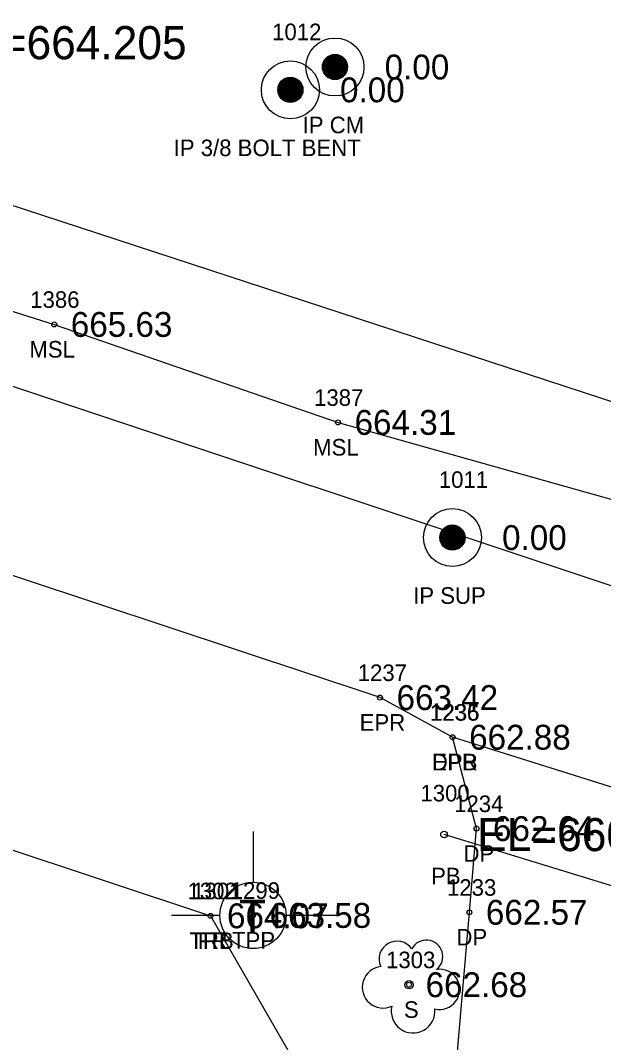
# Model space of a CAD drawing. Extents: x 1655137 to 1657928, y 1003994 to 1005407.
# Drawn here: x 1656195.9 to 1656231.1, y 1004645.1 to 1004706.8 of the extents above; entities that cross this region are included whole.
import ezdxf

# ---------------------------------------------------------------- set-up
doc = ezdxf.new("R2010")
doc.units = 0
for name, color, linetype in [('RD_EX_DR_Pipe', 7, 'Continuous'), ('RD_EX_DR_Pipe_txCode', 7, 'Continuous'), ('RD_EX_Driveway', 7, 'Continuous'), ('RD_EX_Driveway_txCode', 7, 'Continuous'), ('RD_EX_DV_Prop_txCode', 7, 'Continuous'), ('RD_EX_DV_PropPin', 7, 'Continuous'), ('RD_EX_Fence_Other', 7, 'Continuous'), ('RD_EX_Fence_Other_txCode', 7, 'Continuous'), ('RD_EX_Misc', 7, 'Continuous'), ('RD_EX_Misc_txCode', 7, 'Continuous'), ('RD_EX_Road', 7, 'Continuous'), ('RD_EX_Road_txCode', 7, 'Continuous'), ('RD_EX_TX_Driveway_ELEV', 7, 'Continuous'), ('RD_EX_TX_DV_Prop_ELEV', 7, 'Continuous'), ('RD_EX_TX_Fence_Other_ELEV', 7, 'Continuous'), ('RD_EX_TX_Misc_ELEV', 7, 'Continuous'), ('RD_EX_TX_Road_ELEV', 7, 'Continuous'), ('RD_EX_TX_UT_ELEV', 7, 'Continuous'), ('RD_EX_TX_VEG_ELEV', 7, 'Continuous'), ('RD_EX_UT', 7, 'Continuous'), ('RD_EX_UT_txCode', 7, 'Continuous'), ('RD_EX_VEG', 7, 'Continuous'), ('RD_EX_VEG_txCode', 7, 'Continuous'), ('RD_HC_Cl', 7, 'Continuous'), ('RD_SMD_Locator', 7, 'Continuous'), ('RD_TX_Pipe_ElevEX', 7, 'Continuous')]:
    doc.layers.add(name, color=color, linetype=linetype)

msp = doc.modelspace()

# ---------------------------------------------------------------- linework, layer by layer
at = {"layer": 'RD_EX_DR_Pipe'}
msp.add_line((1656241.451, 1004651.596), (1656221.513, 1004657.692), dxfattribs=at)
at = {"layer": 'RD_EX_Driveway'}
msp.add_lwpolyline([(1656244.505, 1004656.516), (1656239.142, 1004653.107), (1656236.385, 1004648.454), (1656232.371, 1004638.136), (1656222.105, 1004642.026), (1656223.042, 1004652.998), (1656223.472, 1004658.051), (1656222.03, 1004663.569)], dxfattribs=at)
at = {"layer": 'RD_EX_DV_PropPin'}
for p, q in [((1656214.263, 1004703.667), (1656214.263, 1004704.406)), ((1656214.298, 1004703.61), (1656214.298, 1004704.463)), ((1656214.333, 1004703.562), (1656214.333, 1004704.51)), ((1656214.368, 1004703.521), (1656214.368, 1004704.551)), ((1656214.403, 1004703.485), (1656214.403, 1004704.587)), ((1656214.438, 1004703.454), (1656214.438, 1004704.618)), ((1656214.473, 1004703.426), (1656214.473, 1004704.646)), ((1656214.508, 1004703.402), (1656214.508, 1004704.671)), ((1656214.543, 1004703.38), (1656214.543, 1004704.693)), ((1656214.578, 1004703.361), (1656214.578, 1004704.712)), ((1656214.613, 1004703.343), (1656214.613, 1004704.729)), ((1656214.648, 1004703.329), (1656214.648, 1004704.744)), ((1656214.683, 1004703.316), (1656214.683, 1004704.757)), ((1656214.718, 1004703.305), (1656214.718, 1004704.768)), ((1656214.753, 1004703.296), (1656214.753, 1004704.777)), ((1656214.788, 1004703.288), (1656214.788, 1004704.784)), ((1656214.823, 1004703.282), (1656214.823, 1004704.79)), ((1656214.858, 1004703.278), (1656214.858, 1004704.794)), ((1656214.893, 1004703.276), (1656214.893, 1004704.796)), ((1656214.928, 1004703.275), (1656214.928, 1004704.797)), ((1656214.963, 1004703.276), (1656214.963, 1004704.796)), ((1656214.998, 1004703.278), (1656214.998, 1004704.794)), ((1656215.033, 1004703.282), (1656215.033, 1004704.79)), ((1656215.068, 1004703.288), (1656215.068, 1004704.784)), ((1656215.103, 1004703.296), (1656215.103, 1004704.777)), ((1656215.138, 1004703.305), (1656215.138, 1004704.768)), ((1656215.173, 1004703.316), (1656215.173, 1004704.757)), ((1656215.208, 1004703.329), (1656215.208, 1004704.744)), ((1656215.243, 1004703.343), (1656215.243, 1004704.729)), ((1656215.278, 1004703.361), (1656215.278, 1004704.712)), ((1656215.313, 1004703.38), (1656215.313, 1004704.693)), ((1656215.348, 1004703.402), (1656215.348, 1004704.671)), ((1656215.383, 1004703.426), (1656215.383, 1004704.646)), ((1656215.418, 1004703.454), (1656215.418, 1004704.618)), ((1656215.453, 1004703.485), (1656215.453, 1004704.587)), ((1656215.488, 1004703.521), (1656215.488, 1004704.551)), ((1656215.523, 1004703.562), (1656215.523, 1004704.51)), ((1656215.558, 1004703.61), (1656215.558, 1004704.463)), ((1656215.593, 1004703.667), (1656215.593, 1004704.406)), ((1656214.193, 1004703.84), (1656214.193, 1004704.232)), ((1656214.228, 1004703.738), (1656214.228, 1004704.334)), ((1656215.628, 1004703.738), (1656215.628, 1004704.334)), ((1656215.663, 1004703.84), (1656215.663, 1004704.232)), ((1656211.674, 1004702.14), (1656211.674, 1004703.17)), ((1656211.709, 1004702.105), (1656211.709, 1004703.206)), ((1656211.744, 1004702.073), (1656211.744, 1004703.238)), ((1656211.779, 1004702.046), (1656211.779, 1004703.265)), ((1656211.814, 1004702.021), (1656211.814, 1004703.29)), ((1656211.849, 1004701.999), (1656211.849, 1004703.312)), ((1656211.884, 1004701.98), (1656211.884, 1004703.331)), ((1656211.919, 1004701.963), (1656211.919, 1004703.348)), ((1656211.954, 1004701.948), (1656211.954, 1004703.363)), ((1656211.989, 1004701.935), (1656211.989, 1004703.376)), ((1656212.024, 1004701.924), (1656212.024, 1004703.387)), ((1656212.059, 1004701.915), (1656212.059, 1004703.396)), ((1656212.094, 1004701.907), (1656212.094, 1004703.403)), ((1656212.129, 1004701.902), (1656212.129, 1004703.409)), ((1656212.164, 1004701.898), (1656212.164, 1004703.413)), ((1656212.199, 1004701.895), (1656212.199, 1004703.416)), ((1656212.234, 1004701.894), (1656212.234, 1004703.416)), ((1656212.269, 1004701.895), (1656212.269, 1004703.416)), ((1656212.304, 1004701.898), (1656212.304, 1004703.413)), ((1656212.339, 1004701.902), (1656212.339, 1004703.409)), ((1656212.374, 1004701.907), (1656212.374, 1004703.403)), ((1656212.409, 1004701.915), (1656212.409, 1004703.396)), ((1656212.444, 1004701.924), (1656212.444, 1004703.387)), ((1656212.479, 1004701.935), (1656212.479, 1004703.376)), ((1656212.514, 1004701.948), (1656212.514, 1004703.363)), ((1656212.549, 1004701.963), (1656212.549, 1004703.348)), ((1656212.584, 1004701.98), (1656212.584, 1004703.331)), ((1656212.619, 1004701.999), (1656212.619, 1004703.312)), ((1656212.654, 1004702.021), (1656212.654, 1004703.29)), ((1656212.689, 1004702.046), (1656212.689, 1004703.265)), ((1656212.724, 1004702.073), (1656212.724, 1004703.238)), ((1656212.759, 1004702.105), (1656212.759, 1004703.206)), ((1656212.795, 1004702.14), (1656212.795, 1004703.17)), ((1656211.499, 1004702.459), (1656211.499, 1004702.852)), ((1656211.534, 1004702.357), (1656211.534, 1004702.953)), ((1656211.569, 1004702.286), (1656211.569, 1004703.025)), ((1656211.604, 1004702.229), (1656211.604, 1004703.082)), ((1656211.639, 1004702.181), (1656211.639, 1004703.13)), ((1656212.83, 1004702.181), (1656212.83, 1004703.13)), ((1656212.865, 1004702.229), (1656212.865, 1004703.082)), ((1656212.9, 1004702.286), (1656212.9, 1004703.025)), ((1656212.935, 1004702.357), (1656212.935, 1004702.953)), ((1656212.97, 1004702.459), (1656212.97, 1004702.852)), ((1656221.354, 1004675.253), (1656221.354, 1004675.992)), ((1656221.389, 1004675.196), (1656221.389, 1004676.049)), ((1656221.424, 1004675.148), (1656221.424, 1004676.097)), ((1656221.459, 1004675.108), (1656221.459, 1004676.138)), ((1656221.494, 1004675.072), (1656221.494, 1004676.173)), ((1656221.529, 1004675.04), (1656221.529, 1004676.205)), ((1656221.564, 1004675.013), (1656221.564, 1004676.232)), ((1656221.599, 1004674.988), (1656221.599, 1004676.257)), ((1656221.634, 1004674.966), (1656221.634, 1004676.279)), ((1656221.669, 1004674.947), (1656221.669, 1004676.298)), ((1656221.704, 1004674.93), (1656221.704, 1004676.315)), ((1656221.739, 1004674.915), (1656221.739, 1004676.33)), ((1656221.774, 1004674.902), (1656221.774, 1004676.343)), ((1656221.809, 1004674.891), (1656221.809, 1004676.354)), ((1656221.844, 1004674.882), (1656221.844, 1004676.363)), ((1656221.879, 1004674.875), (1656221.879, 1004676.371)), ((1656221.914, 1004674.869), (1656221.914, 1004676.376)), ((1656221.949, 1004674.865), (1656221.949, 1004676.38)), ((1656221.984, 1004674.862), (1656221.984, 1004676.383)), ((1656222.019, 1004674.862), (1656222.019, 1004676.384)), ((1656222.054, 1004674.862), (1656222.054, 1004676.383)), ((1656222.089, 1004674.865), (1656222.089, 1004676.38)), ((1656222.124, 1004674.869), (1656222.124, 1004676.376)), ((1656222.159, 1004674.875), (1656222.159, 1004676.371)), ((1656222.194, 1004674.882), (1656222.194, 1004676.363)), ((1656222.229, 1004674.891), (1656222.229, 1004676.354)), ((1656222.264, 1004674.902), (1656222.264, 1004676.343)), ((1656222.299, 1004674.915), (1656222.299, 1004676.33)), ((1656222.334, 1004674.93), (1656222.334, 1004676.315)), ((1656222.369, 1004674.947), (1656222.369, 1004676.298)), ((1656222.404, 1004674.966), (1656222.404, 1004676.279)), ((1656222.439, 1004674.988), (1656222.439, 1004676.257)), ((1656222.474, 1004675.013), (1656222.474, 1004676.232)), ((1656222.509, 1004675.04), (1656222.509, 1004676.205)), ((1656222.544, 1004675.072), (1656222.544, 1004676.173)), ((1656222.579, 1004675.108), (1656222.579, 1004676.138)), ((1656222.614, 1004675.148), (1656222.614, 1004676.097)), ((1656222.649, 1004675.196), (1656222.649, 1004676.049)), ((1656222.684, 1004675.253), (1656222.684, 1004675.992)), ((1656221.284, 1004675.426), (1656221.284, 1004675.819)), ((1656221.319, 1004675.325), (1656221.319, 1004675.921)), ((1656222.719, 1004675.325), (1656222.719, 1004675.921)), ((1656222.754, 1004675.426), (1656222.754, 1004675.819))]:
    msp.add_line(p, q, dxfattribs=at)
for centre, radius in [((1656214.928, 1004704.036), 1.75), ((1656212.234, 1004702.655), 1.75), ((1656214.928, 1004704.036), 0.761), ((1656212.234, 1004702.655), 0.761), ((1656222.019, 1004675.623), 1.75), ((1656222.019, 1004675.623), 0.761)]:
    msp.add_circle(centre, radius, dxfattribs=at)
at = {"layer": 'RD_EX_Fence_Other'}
msp.add_lwpolyline([(1656052.395, 1004677.708), (1656061.837, 1004701.046), (1656117.123, 1004682.782), (1656207.407, 1004652.786), (1656216.442, 1004637.082), (1656207.492, 1004611.283)], dxfattribs=at)
at = {"layer": 'RD_EX_Misc'}
msp.add_lwpolyline([(1655875.572, 1004783.81), (1655899.124, 1004775.727), (1655924.143, 1004767.915), (1655957.486, 1004756.441), (1655982.243, 1004748.48), (1656011.779, 1004739.501), (1656033.158, 1004732.174), (1656057.837, 1004724.625), (1656091.047, 1004714.315), (1656106.296, 1004710.837), (1656119.065, 1004707.85), (1656127.527, 1004711.026), (1656137.413, 1004709.544), (1656150.275, 1004705.031), (1656164.334, 1004699.598), (1656171.578, 1004694.85), (1656180.966, 1004693.871), (1656197.975, 1004688.492), (1656215.111, 1004682.576), (1656240.683, 1004675.392), (1656271.878, 1004665.005), (1656304.44, 1004655.084)], dxfattribs=at)
at = {"layer": 'RD_EX_Road'}
for points in [[(1656365.125, 1004639.993), (1656336.036, 1004649.337), (1656302.553, 1004660.365), (1656279.148, 1004668.232), (1656240.072, 1004681.052), (1656188.234, 1004698.028), (1656166.718, 1004705.508), (1656141.162, 1004714.063), (1656093.113, 1004730.113), (1656044.163, 1004746.75), (1655996.355, 1004762.445), (1655947.197, 1004778.676), (1655899.09, 1004794.03), (1655850.622, 1004809.986), (1655801.911, 1004826.095), (1655753.093, 1004842.312), (1655704.246, 1004858.105)], [(1656358.504, 1004619.827), (1656328.784, 1004629.475), (1656280.774, 1004645.393), (1656247.663, 1004656.111), (1656244.505, 1004656.516), (1656222.03, 1004663.569), (1656217.647, 1004665.963), (1656183.416, 1004677.324), (1656134.594, 1004693.716), (1656086.193, 1004709.749), (1656037.581, 1004726.126), (1655989.575, 1004741.988), (1655940.618, 1004757.879), (1655892.373, 1004773.61), (1655843.478, 1004789.356), (1655805.734, 1004801.404), (1655779.222, 1004810.434), (1655768.796, 1004813.103), (1655744.595, 1004822.13), (1655698.832, 1004837.654)]]:
    msp.add_lwpolyline(points, dxfattribs=at)
at = {"layer": 'RD_EX_UT'}
for p, q in [((1656209.979, 1004657.88), (1656209.979, 1004654.81)), ((1656205.049, 1004652.826), (1656207.979, 1004652.826)), ((1656211.979, 1004652.826), (1656215.049, 1004652.826))]:
    msp.add_line(p, q, dxfattribs=at)
msp.add_circle((1656209.979, 1004652.81), 2, dxfattribs=at)
at = {"layer": 'RD_EX_VEG'}
msp.add_lwpolyline([(1656061.837, 1004701.046), (1656117.123, 1004682.782), (1656207.407, 1004652.786)], dxfattribs=at)
msp.add_circle((1656219.399, 1004648.625), 0.25, dxfattribs=at)
for centre, radius, start, end in [((1656220.444, 1004650.327), 0.995, 308.76261, 152.04674), ((1656218.678, 1004650.172), 1.084, 34.97629, 204.75602), ((1656217.835, 1004648.469), 1.257, 96.45179, 294.73401), ((1656221.239, 1004648.346), 1.218, 256.56668, 98.10463), ((1656219.644, 1004647.029), 1.318, 166.88266, 5.75893)]:
    msp.add_arc(centre, radius, start, end, dxfattribs=at)
at = {"layer": 'RD_HC_Cl'}
msp.add_line((1656069.258, 1004726.842), (1656507.359, 1004580.769), dxfattribs=at)
at = {"layer": 'RD_SMD_Locator'}
for centre, radius in [((1656214.928, 1004704.036), 0.15), ((1656212.234, 1004702.655), 0.15), ((1656197.975, 1004688.492), 0.15), ((1656215.111, 1004682.576), 0.15), ((1656222.019, 1004675.623), 0.15), ((1656217.647, 1004665.963), 0.15), ((1656222.03, 1004663.569), 0.15), ((1656222.03, 1004663.569), 0.15), ((1656223.472, 1004658.051), 0.15), ((1656221.513, 1004657.692), 0.2), ((1656223.042, 1004652.998), 0.15), ((1656207.407, 1004652.786), 0.15), ((1656207.407, 1004652.786), 0.15), ((1656209.979, 1004652.81), 0.15), ((1656219.399, 1004648.625), 0.15)]:
    msp.add_circle(centre, radius, dxfattribs=at)

# ---------------------------------------------------------------- texts
at = {"layer": 'RD_EX_DR_Pipe_txCode'}
for s, p in [('1300', (1656220.088, 1004659.692)), ('PB', (1656220.734, 1004654.692))]:
    msp.add_text(s, height=1, dxfattribs=at).set_placement(p)
at = {"layer": 'RD_EX_Driveway_txCode'}
for s, p in [('1235', (1656220.684, 1004664.569)), ('DPB', (1656220.778, 1004661.569)), ('1234', (1656222.126, 1004659.051)), ('DP', (1656222.693, 1004656.051)), ('1233', (1656221.695, 1004653.998)), ('DP', (1656222.262, 1004650.998))]:
    msp.add_text(s, height=1, dxfattribs=at).set_placement(p)
at = {"layer": 'RD_EX_DV_Prop_txCode'}
for s, p in [('1012', (1656211.132, 1004705.655)), ('IP CM', (1656212.975, 1004700.036)), ('IP 3/8 BOLT BENT', (1656205.187, 1004698.655)), ('1011', (1656221.2, 1004678.623)), ('IP SUP', (1656219.649, 1004671.623))]:
    msp.add_text(s, height=1, dxfattribs=at).set_placement(p)
at = {"layer": 'RD_EX_Fence_Other_txCode'}
for s, p in [('1301', (1656206.305, 1004653.786)), ('FR', (1656206.651, 1004650.786))]:
    msp.add_text(s, height=1, dxfattribs=at).set_placement(p)
at = {"layer": 'RD_EX_Misc_txCode'}
for s, p in [('1386', (1656196.526, 1004689.492)), ('MSL', (1656196.473, 1004686.492)), ('1387', (1656213.667, 1004683.576)), ('MSL', (1656213.609, 1004680.576))]:
    msp.add_text(s, height=1, dxfattribs=at).set_placement(p)
at = {"layer": 'RD_EX_Road_txCode'}
for s, p in [('1237', (1656216.301, 1004666.963)), ('1236', (1656220.66, 1004664.569)), ('EPR', (1656216.419, 1004663.963)), ('EPR', (1656220.802, 1004661.569))]:
    msp.add_text(s, height=1, dxfattribs=at).set_placement(p)
at = {"layer": 'RD_EX_TX_Driveway_ELEV'}
for s, p in [('662.88', (1656223.03, 1004662.819)), ('662.64', (1656224.472, 1004657.301)), ('662.57', (1656224.042, 1004652.248))]:
    msp.add_text(s, height=1.5, dxfattribs=at).set_placement(p)
at = {"layer": 'RD_EX_TX_DV_Prop_ELEV'}
for p in [(1656217.928, 1004703.286), (1656215.234, 1004701.905), (1656225.019, 1004674.873)]:
    msp.add_text('0.00', height=1.5, dxfattribs=at).set_placement(p)
at = {"layer": 'RD_EX_TX_Fence_Other_ELEV'}
msp.add_text('664.07', height=1.5, dxfattribs=at).set_placement((1656208.407, 1004652.036))
at = {"layer": 'RD_EX_TX_Misc_ELEV'}
for s, p in [('665.63', (1656198.975, 1004687.742)), ('664.31', (1656216.111, 1004681.826))]:
    msp.add_text(s, height=1.5, dxfattribs=at).set_placement(p)
at = {"layer": 'RD_EX_TX_Road_ELEV'}
for s, p in [('663.42', (1656218.647, 1004665.213)), ('662.88', (1656223.03, 1004662.819))]:
    msp.add_text(s, height=1.5, dxfattribs=at).set_placement(p)
at = {"layer": 'RD_EX_TX_UT_ELEV'}
msp.add_text('663.58', height=1.5, dxfattribs=at).set_placement((1656210.979, 1004652.06))
at = {"layer": 'RD_EX_TX_VEG_ELEV'}
for s, p in [('664.07', (1656208.407, 1004652.036)), ('662.68', (1656220.399, 1004647.875))]:
    msp.add_text(s, height=1.5, dxfattribs=at).set_placement(p)
at = {"layer": 'RD_EX_UT'}
msp.add_text('T', height=2, dxfattribs=at).set_placement((1656209.13, 1004651.763))
at = {"layer": 'RD_EX_UT_txCode'}
for s, p in [('1299', (1656208.633, 1004653.81)), ('TPP', (1656208.712, 1004650.81))]:
    msp.add_text(s, height=1, dxfattribs=at).set_placement(p)
at = {"layer": 'RD_EX_VEG_txCode'}
for s, p in [('1302', (1656206.021, 1004653.786)), ('TRB', (1656206.139, 1004650.786)), ('1303', (1656218.013, 1004649.625)), ('S', (1656219.092, 1004646.625))]:
    msp.add_text(s, height=1, dxfattribs=at).set_placement(p)
at = {"layer": 'RD_TX_Pipe_ElevEX'}
for s, p in [('EL=664.205', (1656191.469, 1004704.504)), ('EL=660.770', (1656223.513, 1004656.692))]:
    msp.add_text(s, height=2, dxfattribs=at).set_placement(p)

doc.saveas('drawing.dxf')
